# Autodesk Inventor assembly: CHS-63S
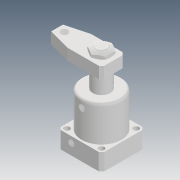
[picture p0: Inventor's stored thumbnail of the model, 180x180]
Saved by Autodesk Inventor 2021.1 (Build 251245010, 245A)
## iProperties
Created: 2019-05
Part Number: CHS-63S
Description: STEP AP203
Document SubType Name: Assembly
Designer: user
Title: chs-63s_asm.STEP
Revision Number: ÈÎºÎ
Sending System: SolidWorks 2017
Preprocessor: SwSTEP 2.0
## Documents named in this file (5)
- D:\Vault_2016\Projekty\Clamptek\Hydraulic\CHS\CHS-63\Inventor\CHS-63S\CHS-63S.iam
- D:\Vault_2016\Projekty\Clamptek\Hydraulic\CHS\CHS-63\Inventor\CHS-63S\CHS-63-03_1.ipt
- D:\Vault_2016\Projekty\Clamptek\Hydraulic\CHS\CHS-63\Inventor\CHS-63S\CHS-63S-02_2.ipt
- D:\Vault_2016\Projekty\Clamptek\Hydraulic\CHS\CHS-63\Inventor\CHS-63S\CHS-63S-01_2.ipt
- D:\Vault_2016\Projekty\Clamptek\Hydraulic\CHS\CHS-63\Inventor\CHS-63S\M24_2.ipt
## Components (4 placed, 4 different names)
1. CHS-63-03_1_1
2. CHS-63S-02_2_2
3. CHS-63S-01_2_3
4. M24_2_4
